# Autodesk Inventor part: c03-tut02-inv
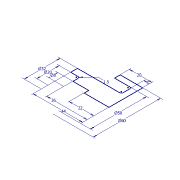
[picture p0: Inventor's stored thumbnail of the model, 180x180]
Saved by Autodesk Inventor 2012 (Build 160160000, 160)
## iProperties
Created: 2010-01
Part Number: c03-tut02-inv
Document SubType Name: Modeling
Designer: CADSoft
Density: 1 g/cm^3
Material: Default
Author: CADSoft
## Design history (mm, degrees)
sketch "Sketch1"
  geometry: L1 (22, 0)-(22, 30); L2 (22, 30)-(2, 30); L3 (2, 30)-(2, 25); L4 (2, 25)-(15.5, 25); L5 (17, 23.5)-(17, 17.5); L6 (15.5, 16)-(-22, 16); L7 (-22, 16)-(-22, 10); L8 (-22, 10)-(-15.5, 10); L9 (-14, 8.5)-(-14, 4); L10 (-14, 4)-(0, 4); L11 (0, 4)-(0, 0); L12 (0, 0)-(22, 0); A1 r 1.5 centre (-15.5, 8.5) between (-14, 8.5) and (-15.5, 10); A2 r 1.5 centre (15.5, 23.5) between (17, 23.5) and (15.5, 25); A3 r 1.5 centre (15.5, 17.5) between (15.5, 16) and (17, 17.5); 2 further points
  constraints: 24 end point, 6 point on circle, 6 tangent, 3 centre point, 2 coincident, 2 equal radius, 2 vertical, 1 horizontal, 1 other
  dimensions: "d0" = 8 diameter of L10 L12; "d1" = 20 diameter of L8 L12; "d2" = 32 diameter of L6 L12; "d3" = 50 diameter of L4 L12; "d5" = 60 diameter of L2 L12; "d6" = 5 distance between parallel lines of L5 L1; "d7" = 20 distance of L1.end L2.end; "d8" = 22 distance of L11.end L1.start; "d9" = 36 distance between parallel lines of L9 L1; "d10" = 44 distance between parallel lines of L7 L1; "d11" = 1.5 radius of A1
